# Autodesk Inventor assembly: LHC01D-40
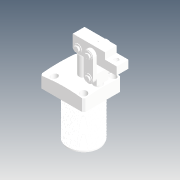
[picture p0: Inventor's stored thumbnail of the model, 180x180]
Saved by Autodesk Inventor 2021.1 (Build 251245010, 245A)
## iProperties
Created: 2019-04
Part Number: LHC01D-40
Description: STEP AP214
Document SubType Name: Assembly
Designer: user
Title: LHC01D-40.STEP
Revision Number: ÈÎºÎ
Sending System: SolidWorks 2016
Preprocessor: SwSTEP 2.0
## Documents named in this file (12)
- D:\Vault_2016\Projekty\Clamptek\Hydraulic\LHC01D\Inventor\LHC01D-40\LHC01D-40.iam
- D:\Vault_2016\Projekty\Clamptek\Hydraulic\LHC01D\Inventor\LHC01D-40\LHC01D-40-07.ipt
- D:\Vault_2016\Projekty\Clamptek\Hydraulic\LHC01D\Inventor\LHC01D-40\LHC01D40»îÈû¸Ë.ipt
- D:\Vault_2016\Projekty\Clamptek\Hydraulic\LHC01D\Inventor\LHC01D-40\CPLCU-40ZCK.ipt
- D:\Vault_2016\Projekty\Clamptek\Hydraulic\LHC01D\Inventor\LHC01D-40\CPLCU-40YB.ipt
- D:\Vault_2016\Projekty\Clamptek\Hydraulic\LHC01D\Inventor\LHC01D-40\CPLCU-40LG.ipt
- D:\Vault_2016\Projekty\Clamptek\Hydraulic\LHC01D\Inventor\LHC01D-40\CPLCU-40DX.ipt
- D:\Vault_2016\Projekty\Clamptek\Hydraulic\LHC01D\Inventor\LHC01D-40\CPLCU-40X.ipt
- D:\Vault_2016\Projekty\Clamptek\Hydraulic\LHC01D\Inventor\LHC01D-40\LHC01D-40-05.ipt
- D:\Vault_2016\Projekty\Clamptek\Hydraulic\LHC01D\Inventor\LHC01D-40\LHC01D-40-08.ipt
- D:\Vault_2016\Projekty\Clamptek\Hydraulic\LHC01D\Inventor\LHC01D-40\M4ningjin_4.ipt
- D:\Vault_2016\Projekty\Clamptek\Hydraulic\LHC01D\Inventor\LHC01D-40\¶ÂÍ·_7.ipt
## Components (24 placed, 24 different names)
1. LHC01D-40-07_1
2. LHC01D40»îÈû¸Ë_2
3. CPLCU-40ZCK_3
4. CPLCU-40YB_4
5. CPLCU-40LG_5
6. CPLCU-40LG_6
7. CPLCU-40DX_7
8. CPLCU-40X_8
9. CPLCU-40X_9
10. LHC01D-40-05_10
11. LHC01D-40-05_11
12. LHC01D-40-05_12
13. LHC01D-40-05_13
14. LHC01D-40-05_14
15. LHC01D-40-05_15
16. LHC01D-40-08_16
17. LHC01D-40-08_17
18. LHC01D-40-08_18
19. LHC01D-40-08_19
20. LHC01D-40-08_20
21. LHC01D-40-08_21
22. M4ningjin_4_22
23. ¶ÂÍ·_7_23
24. ¶ÂÍ·_7_24
